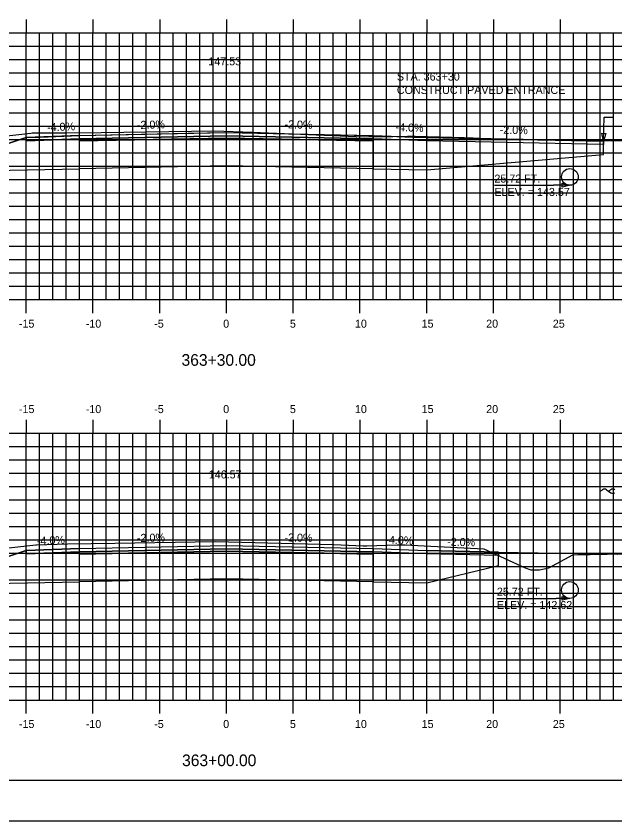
# Model space of a CAD drawing. Extents: x 1146968 to 1147138, y 608981 to 609091.
# Drawn here: x 1147035.4 to 1147080.3, y 608981.3 to 609041.6 of the extents above; entities that cross this region are included whole.
import ezdxf

# ---------------------------------------------------------------- set-up
doc = ezdxf.new("R2010")
doc.units = 0
for name, color, linetype in [('ANNOTATION', 7, 'Continuous'), ('BORDER', 7, 'Continuous'), ('D_Drainage_Culvert', 7, 'Continuous'), ('D_Roadway_Centerline', 7, 'Continuous'), ('D_Roadway_Centerline_Text', 7, 'Continuous'), ('D_Roadway_Edge_Shoulder', 7, 'Continuous'), ('D_Roadway_Edge_TW', 7, 'Continuous'), ('D_Roadway_Pavement', 7, 'Continuous'), ('D_Roadway_SubGrade', 7, 'Continuous'), ('D_Text_Standard', 7, 'Continuous'), ('D_Utilities_Pole_Joint_Rt', 7, 'Continuous'), ('H_V ANNOTATION', 7, 'Continuous'), ('MAJOR', 7, 'Continuous'), ('MINOR', 7, 'Continuous'), ('PLOT BOUNDARY', 7, 'Continuous'), ('S_Roadway_Centerline', 7, 'Continuous')]:
    doc.layers.add(name, color=color, linetype=linetype)

msp = doc.modelspace()

# ---------------------------------------------------------------- linework, layer by layer
for points in [[(1147030.469, 609030.576), (1147036.183, 609032.48), (1147036.184, 609032.48), (1147036.184, 609032.48), (1147037.225, 609032.522), (1147040.184, 609032.64), (1147048.322, 609032.803), (1147051.184, 609032.86), (1147059.322, 609032.697), (1147062.184, 609032.64), (1147065.144, 609032.522), (1147066.184, 609032.48), (1147075.982, 609032.284), (1147079.429, 609032.215)], [(1147013.409, 609002.682), (1147014.659, 609002.625), (1147015.909, 609002.405), (1147017.159, 609002.023), (1147018.409, 609001.479), (1147025.46, 608997.953), (1147028.46, 608998.953), (1147036.183, 609001.528), (1147036.184, 609001.528), (1147040.184, 609001.688), (1147051.184, 609001.908), (1147062.184, 609001.688), (1147066.184, 609001.528), (1147071.549, 609001.42)]]:
    msp.add_lwpolyline(points)
at = {"layer": 'BORDER'}
msp.add_lwpolyline([(1146976.185, 608984.335), (1147136.185, 608984.335), (1147136.185, 609089.335), (1146976.185, 609089.335)], close=True, dxfattribs=at)
at = {"layer": 'D_Drainage_Culvert'}
for centre in [(1147076.908, 609029.531), (1147076.908, 608998.578)]:
    msp.add_circle(centre, 0.625, dxfattribs=at)
at = {"layer": 'D_Roadway_Edge_Shoulder'}
for points in [[(1147040.184, 609032.64), (1147036.184, 609032.48), (1147036.184, 609032.23), (1147040.184, 609032.39)], [(1147062.184, 609032.64), (1147066.184, 609032.48), (1147066.184, 609032.23), (1147062.184, 609032.39)], [(1147066.184, 609032.48), (1147079.429, 609032.215), (1147079.429, 609031.965), (1147066.184, 609032.23)], [(1147040.184, 609001.688), (1147036.184, 609001.528), (1147036.184, 609001.278), (1147040.184, 609001.438)], [(1147062.184, 609001.688), (1147066.184, 609001.528), (1147066.184, 609001.278), (1147062.184, 609001.438)], [(1147066.184, 609001.528), (1147071.549, 609001.42), (1147071.549, 609001.17), (1147066.184, 609001.278)]]:
    msp.add_lwpolyline(points, close=True, dxfattribs=at)
at = {"layer": 'D_Roadway_Edge_TW'}
for points in [[(1147040.184, 609032.39), (1147040.184, 609032.64), (1147051.184, 609032.86), (1147062.184, 609032.64), (1147062.184, 609032.39), (1147051.184, 609032.61)], [(1147040.184, 609001.438), (1147040.184, 609001.688), (1147051.184, 609001.908), (1147062.184, 609001.688), (1147062.184, 609001.438), (1147051.184, 609001.658)]]:
    msp.add_lwpolyline(points, close=True, dxfattribs=at)
at = {"layer": 'D_Roadway_Pavement'}
for points in [[(1147040.184, 609032.223), (1147040.184, 609032.39), (1147051.184, 609032.61), (1147062.184, 609032.39), (1147062.184, 609032.223), (1147051.184, 609032.443)], [(1147040.184, 609001.271), (1147040.184, 609001.438), (1147051.184, 609001.658), (1147062.184, 609001.438), (1147062.184, 609001.271), (1147051.184, 609001.491)]]:
    msp.add_lwpolyline(points, close=True, dxfattribs=at)
at = {"layer": 'D_Roadway_SubGrade'}
msp.add_line((1147071.549, 609001.42), (1147080.474, 609001.271), dxfattribs=at)
for points in [[(1147040.184, 609032.223), (1147040.184, 609032.39), (1147036.184, 609032.23), (1147036.184, 609032.48), (1147036.183, 609032.48), (1147028.46, 609029.906), (1147040.184, 609030.14)], [(1147040.184, 609030.14), (1147040.184, 609032.223), (1147051.184, 609032.443), (1147062.184, 609032.223), (1147062.184, 609030.14), (1147051.184, 609030.36)], [(1147079.429, 609031.215), (1147079.429, 609032.215), (1147066.184, 609032.48), (1147066.184, 609032.23), (1147062.184, 609032.39), (1147062.184, 609032.223), (1147062.184, 609030.14), (1147066.184, 609030.06)], [(1147040.184, 609001.271), (1147040.184, 609001.438), (1147036.184, 609001.278), (1147036.184, 609001.528), (1147036.183, 609001.528), (1147028.46, 608998.953), (1147040.184, 608999.188)], [(1147040.184, 608999.188), (1147040.184, 609001.271), (1147051.184, 609001.491), (1147062.184, 609001.271), (1147062.184, 608999.188), (1147051.184, 608999.408)], [(1147071.549, 609000.42), (1147071.549, 609001.42), (1147066.184, 609001.528), (1147066.184, 609001.278), (1147062.184, 609001.438), (1147062.184, 609001.271), (1147062.184, 608999.188), (1147066.184, 608999.108)]]:
    msp.add_lwpolyline(points, close=True, dxfattribs=at)
at = {"layer": 'D_Text_Standard'}
for p, q in [((1147071.256, 609028.906), (1147075.692, 609028.906)), ((1147071.439, 608997.953), (1147075.875, 608997.953))]:
    msp.add_line(p, q, dxfattribs=at)
for points in [[(1147079.429, 609032.215), (1147079.466, 609033.997), (1147080.146, 609033.997)], [(1147076.908, 609028.906), (1147076.372, 609028.906), (1147075.692, 609028.906)], [(1147076.908, 608997.953), (1147076.555, 608997.953), (1147075.875, 608997.953)]]:
    msp.add_lwpolyline(points, dxfattribs=at)
for points in [[(1147079.429, 609032.215), (1147079.296, 609032.8), (1147079.587, 609032.794)], [(1147076.908, 609028.906), (1147076.326, 609028.76), (1147076.326, 609029.051)], [(1147076.908, 608997.953), (1147076.326, 608997.808), (1147076.326, 608998.099)]]:
    msp.add_lwpolyline(points, close=True, dxfattribs=at)
at = {"layer": 'D_Utilities_Pole_Joint_Rt'}
for p, q in [((1147079.184, 609005.978), (1147079.34, 609006.088)), ((1147079.184, 609001.22), (1147079.184, 609005.978)), ((1147079.653, 609006.088), (1147079.809, 609005.978)), ((1147079.965, 609006.088), (1147079.809, 609005.978)), ((1147079.809, 609005.978), (1147079.965, 609005.867))]:
    msp.add_line(p, q, dxfattribs=at)
for centre, start, end in [((1147079.497, 609005.867), 90, 125.26439), ((1147079.497, 609005.867), 54.73561, 90), ((1147080.122, 609005.867), 90, 125.26439), ((1147080.122, 609006.088), 234.73561, 270), ((1147080.122, 609005.867), 54.73561, 90), ((1147080.122, 609006.088), 270, 305.26439)]:
    msp.add_arc(centre, 0.271, start, end, dxfattribs=at)
at = {"layer": 'MAJOR'}
for p, q in [((1147036.184, 609041.337), (1147036.184, 609040.335)), ((1147041.184, 609041.337), (1147041.184, 609040.335)), ((1147046.184, 609041.337), (1147046.184, 609040.335)), ((1147051.184, 609041.337), (1147051.184, 609040.335)), ((1147056.184, 609041.337), (1147056.184, 609040.335)), ((1147061.184, 609041.337), (1147061.184, 609040.335)), ((1147066.184, 609041.337), (1147066.184, 609040.335)), ((1147071.184, 609041.337), (1147071.184, 609040.335)), ((1147076.184, 609041.337), (1147076.184, 609040.335)), ((1146981.184, 609040.335), (1147121.184, 609040.335)), ((1146981.184, 609040.335), (1147121.184, 609040.335)), ((1147036.184, 609020.335), (1147036.184, 609040.335)), ((1147041.184, 609020.335), (1147041.184, 609040.335)), ((1147046.184, 609020.335), (1147046.184, 609040.335)), ((1147051.184, 609020.335), (1147051.184, 609040.335)), ((1147056.184, 609020.335), (1147056.184, 609040.335)), ((1147061.184, 609020.335), (1147061.184, 609040.335)), ((1147066.184, 609020.335), (1147066.184, 609040.335)), ((1147071.184, 609020.335), (1147071.184, 609040.335)), ((1147076.184, 609020.335), (1147076.184, 609040.335)), ((1146981.184, 609035.335), (1147121.184, 609035.335)), ((1146981.184, 609030.335), (1147121.184, 609030.335)), ((1146981.184, 609025.335), (1147121.184, 609025.335)), ((1146981.184, 609020.335), (1147121.184, 609020.335)), ((1146981.184, 609020.335), (1147121.184, 609020.335)), ((1147036.184, 609019.333), (1147036.184, 609020.335)), ((1147041.184, 609019.333), (1147041.184, 609020.335)), ((1147046.184, 609019.333), (1147046.184, 609020.335)), ((1147051.184, 609019.333), (1147051.184, 609020.335)), ((1147056.184, 609019.333), (1147056.184, 609020.335)), ((1147061.184, 609019.333), (1147061.184, 609020.335)), ((1147066.184, 609019.333), (1147066.184, 609020.335)), ((1147071.184, 609019.333), (1147071.184, 609020.335)), ((1147076.184, 609019.333), (1147076.184, 609020.335)), ((1147036.184, 609011.337), (1147036.184, 609010.335)), ((1147041.184, 609011.337), (1147041.184, 609010.335)), ((1147046.184, 609011.337), (1147046.184, 609010.335)), ((1147051.184, 609011.337), (1147051.184, 609010.335)), ((1147056.184, 609011.337), (1147056.184, 609010.335)), ((1147061.184, 609011.337), (1147061.184, 609010.335)), ((1147066.184, 609011.337), (1147066.184, 609010.335)), ((1147071.184, 609011.337), (1147071.184, 609010.335)), ((1147076.184, 609011.337), (1147076.184, 609010.335)), ((1146981.184, 609010.335), (1147121.184, 609010.335)), ((1146981.184, 609010.335), (1147121.184, 609010.335)), ((1147036.184, 608990.335), (1147036.184, 609010.335)), ((1147041.184, 608990.335), (1147041.184, 609010.335)), ((1147046.184, 608990.335), (1147046.184, 609010.335)), ((1147051.184, 608990.335), (1147051.184, 609010.335)), ((1147056.184, 608990.335), (1147056.184, 609010.335)), ((1147061.184, 608990.335), (1147061.184, 609010.335)), ((1147066.184, 608990.335), (1147066.184, 609010.335)), ((1147071.184, 608990.335), (1147071.184, 609010.335)), ((1147076.184, 608990.335), (1147076.184, 609010.335)), ((1146981.184, 609005.335), (1147121.184, 609005.335)), ((1146981.184, 609000.335), (1147121.184, 609000.335)), ((1146981.184, 608995.335), (1147121.184, 608995.335)), ((1146981.184, 608990.335), (1147121.184, 608990.335)), ((1146981.184, 608990.335), (1147121.184, 608990.335)), ((1147036.184, 608989.333), (1147036.184, 608990.335)), ((1147041.184, 608989.333), (1147041.184, 608990.335)), ((1147046.184, 608989.333), (1147046.184, 608990.335)), ((1147051.184, 608989.333), (1147051.184, 608990.335)), ((1147056.184, 608989.333), (1147056.184, 608990.335)), ((1147061.184, 608989.333), (1147061.184, 608990.335)), ((1147066.184, 608989.333), (1147066.184, 608990.335)), ((1147071.184, 608989.333), (1147071.184, 608990.335)), ((1147076.184, 608989.333), (1147076.184, 608990.335))]:
    msp.add_line(p, q, dxfattribs=at)
at = {"layer": 'MINOR'}
for p, q in [((1147037.184, 609020.335), (1147037.184, 609040.335)), ((1147038.184, 609020.335), (1147038.184, 609040.335)), ((1147039.184, 609020.335), (1147039.184, 609040.335)), ((1147040.184, 609020.335), (1147040.184, 609040.335)), ((1147042.184, 609020.335), (1147042.184, 609040.335)), ((1147043.184, 609020.335), (1147043.184, 609040.335)), ((1147044.184, 609020.335), (1147044.184, 609040.335)), ((1147045.184, 609020.335), (1147045.184, 609040.335)), ((1147047.184, 609020.335), (1147047.184, 609040.335)), ((1147048.184, 609020.335), (1147048.184, 609040.335)), ((1147049.184, 609020.335), (1147049.184, 609040.335)), ((1147050.184, 609020.335), (1147050.184, 609040.335)), ((1147052.184, 609020.335), (1147052.184, 609040.335)), ((1147053.184, 609020.335), (1147053.184, 609040.335)), ((1147054.184, 609020.335), (1147054.184, 609040.335)), ((1147055.184, 609020.335), (1147055.184, 609040.335)), ((1147057.184, 609020.335), (1147057.184, 609040.335)), ((1147058.184, 609020.335), (1147058.184, 609040.335)), ((1147059.184, 609020.335), (1147059.184, 609040.335)), ((1147060.184, 609020.335), (1147060.184, 609040.335)), ((1147062.184, 609020.335), (1147062.184, 609040.335)), ((1147063.184, 609020.335), (1147063.184, 609040.335)), ((1147064.184, 609020.335), (1147064.184, 609040.335)), ((1147065.184, 609020.335), (1147065.184, 609040.335)), ((1147067.184, 609020.335), (1147067.184, 609040.335)), ((1147068.184, 609020.335), (1147068.184, 609040.335)), ((1147069.184, 609020.335), (1147069.184, 609040.335)), ((1147070.184, 609020.335), (1147070.184, 609040.335)), ((1147072.184, 609020.335), (1147072.184, 609040.335)), ((1147073.184, 609020.335), (1147073.184, 609040.335)), ((1147074.184, 609020.335), (1147074.184, 609040.335)), ((1147075.184, 609020.335), (1147075.184, 609040.335)), ((1147077.184, 609020.335), (1147077.184, 609040.335)), ((1147078.184, 609020.335), (1147078.184, 609040.335)), ((1147079.184, 609020.335), (1147079.184, 609040.335)), ((1147080.184, 609020.335), (1147080.184, 609040.335)), ((1146981.184, 609039.335), (1147121.184, 609039.335)), ((1146981.184, 609038.335), (1147121.184, 609038.335)), ((1146981.184, 609037.335), (1147121.184, 609037.335)), ((1146981.184, 609036.335), (1147121.184, 609036.335)), ((1146981.184, 609034.335), (1147121.184, 609034.335)), ((1146981.184, 609033.335), (1147121.184, 609033.335)), ((1146981.184, 609032.335), (1147121.184, 609032.335)), ((1146981.184, 609031.335), (1147121.184, 609031.335)), ((1146981.184, 609029.335), (1147121.184, 609029.335)), ((1146981.184, 609028.335), (1147121.184, 609028.335)), ((1146981.184, 609027.335), (1147121.184, 609027.335)), ((1146981.184, 609026.335), (1147121.184, 609026.335)), ((1146981.184, 609024.335), (1147121.184, 609024.335)), ((1146981.184, 609023.335), (1147121.184, 609023.335)), ((1146981.184, 609022.335), (1147121.184, 609022.335)), ((1146981.184, 609021.335), (1147121.184, 609021.335)), ((1147037.184, 608990.335), (1147037.184, 609010.335)), ((1147038.184, 608990.335), (1147038.184, 609010.335)), ((1147039.184, 608990.335), (1147039.184, 609010.335)), ((1147040.184, 608990.335), (1147040.184, 609010.335)), ((1147042.184, 608990.335), (1147042.184, 609010.335)), ((1147043.184, 608990.335), (1147043.184, 609010.335)), ((1147044.184, 608990.335), (1147044.184, 609010.335)), ((1147045.184, 608990.335), (1147045.184, 609010.335)), ((1147047.184, 608990.335), (1147047.184, 609010.335)), ((1147048.184, 608990.335), (1147048.184, 609010.335)), ((1147049.184, 608990.335), (1147049.184, 609010.335)), ((1147050.184, 608990.335), (1147050.184, 609010.335)), ((1147052.184, 608990.335), (1147052.184, 609010.335)), ((1147053.184, 608990.335), (1147053.184, 609010.335)), ((1147054.184, 608990.335), (1147054.184, 609010.335)), ((1147055.184, 608990.335), (1147055.184, 609010.335)), ((1147057.184, 608990.335), (1147057.184, 609010.335)), ((1147058.184, 608990.335), (1147058.184, 609010.335)), ((1147059.184, 608990.335), (1147059.184, 609010.335)), ((1147060.184, 608990.335), (1147060.184, 609010.335)), ((1147062.184, 608990.335), (1147062.184, 609010.335)), ((1147063.184, 608990.335), (1147063.184, 609010.335)), ((1147064.184, 608990.335), (1147064.184, 609010.335)), ((1147065.184, 608990.335), (1147065.184, 609010.335)), ((1147067.184, 608990.335), (1147067.184, 609010.335)), ((1147068.184, 608990.335), (1147068.184, 609010.335)), ((1147069.184, 608990.335), (1147069.184, 609010.335)), ((1147070.184, 608990.335), (1147070.184, 609010.335)), ((1147072.184, 608990.335), (1147072.184, 609010.335)), ((1147073.184, 608990.335), (1147073.184, 609010.335)), ((1147074.184, 608990.335), (1147074.184, 609010.335)), ((1147075.184, 608990.335), (1147075.184, 609010.335)), ((1147077.184, 608990.335), (1147077.184, 609010.335)), ((1147078.184, 608990.335), (1147078.184, 609010.335)), ((1147079.184, 608990.335), (1147079.184, 609010.335)), ((1147080.184, 608990.335), (1147080.184, 609010.335)), ((1146981.184, 609009.335), (1147121.184, 609009.335)), ((1146981.184, 609008.335), (1147121.184, 609008.335)), ((1146981.184, 609007.335), (1147121.184, 609007.335)), ((1146981.184, 609006.335), (1147121.184, 609006.335)), ((1146981.184, 609004.335), (1147121.184, 609004.335)), ((1146981.184, 609003.335), (1147121.184, 609003.335)), ((1146981.184, 609002.335), (1147121.184, 609002.335)), ((1146981.184, 609001.335), (1147121.184, 609001.335)), ((1146981.184, 608999.335), (1147121.184, 608999.335)), ((1146981.184, 608998.335), (1147121.184, 608998.335)), ((1146981.184, 608997.335), (1147121.184, 608997.335)), ((1146981.184, 608996.335), (1147121.184, 608996.335)), ((1146981.184, 608994.335), (1147121.184, 608994.335)), ((1146981.184, 608993.335), (1147121.184, 608993.335)), ((1146981.184, 608992.335), (1147121.184, 608992.335)), ((1146981.184, 608991.335), (1147121.184, 608991.335))]:
    msp.add_line(p, q, dxfattribs=at)
at = {"layer": 'PLOT BOUNDARY'}
msp.add_lwpolyline([(1146968.091, 608981.276), (1147138.091, 608981.276), (1147138.091, 609091.276), (1146968.091, 609091.276)], close=True, dxfattribs=at)
at = {"layer": 'S_Roadway_Centerline'}
for points in [[(1147032.902, 609032.414), (1147036.544, 609032.814), (1147036.638, 609032.827), (1147036.717, 609032.828), (1147039.178, 609032.83), (1147041.813, 609032.859), (1147050.267, 609032.976), (1147053.128, 609032.886), (1147061.491, 609032.54), (1147061.851, 609032.551), (1147063.335, 609032.563), (1147063.654, 609032.562), (1147064.737, 609032.597), (1147065.095, 609032.59), (1147065.314, 609032.584), (1147068.986, 609032.481), (1147069.403, 609032.467), (1147069.668, 609032.456), (1147071.555, 609032.368), (1147074.477, 609032.306), (1147081.694, 609032.225)], [(1147032.634, 609001.482), (1147036.91, 609001.96), (1147036.935, 609001.963), (1147036.96, 609001.964), (1147039.276, 609002.034), (1147042.815, 609002.088), (1147050.33, 609002.201), (1147059.222, 609001.979), (1147061.413, 609001.889), (1147061.458, 609001.89), (1147061.646, 609001.892), (1147061.687, 609001.891), (1147063.974, 609001.967), (1147063.981, 609001.967), (1147063.986, 609001.967), (1147064.574, 609001.95), (1147065.987, 609001.886), (1147070.463, 609001.666), (1147073.56, 609000.239), (1147073.991, 609000.098), (1147074.629, 609000.08), (1147075.325, 609000.242), (1147077.117, 609001.224), (1147081.001, 609001.278)]]:
    msp.add_lwpolyline(points, dxfattribs=at)

# ---------------------------------------------------------------- texts
at = {"layer": 'ANNOTATION'}
for s, p in [('STA. 363+30', (1147063.95, 609036.749)), ('CONSTRUCT PAVED ENTRANCE', (1147063.95, 609035.747))]:
    msp.add_text(s, height=0.6, dxfattribs=at).set_placement(p)
for s, rotation, p in [('-4.0%', 2.29061, (1147037.76, 609032.944)), ('-2.0%', 1.14576, (1147044.487, 609033.126)), ('-2.0%', 358.85424, (1147055.527, 609033.174)), ('-4.0%', 357.70939, (1147063.84, 609032.975)), ('-2.0%', 358.85424, (1147071.65, 609032.771)), ('-4.0%', 2.29061, (1147037, 609001.961)), ('-2.0%', 1.14576, (1147044.487, 609002.174)), ('-2.0%', 358.85424, (1147055.527, 609002.221)), ('-4.0%', 357.70939, (1147063.08, 609002.053)), ('-2.0%', 358.85424, (1147067.71, 609001.897))]:
    msp.add_text(s, height=0.6, rotation=rotation, dxfattribs=at).set_placement(p)
at = {"layer": 'D_Roadway_Centerline'}
for s, p in [('C', (1147051.179, 609032.86)), ('L', (1147051.184, 609032.853)), ('C', (1147051.179, 609001.908)), ('L', (1147051.184, 609001.9))]:
    msp.add_text(s, height=0.0146, dxfattribs=at).set_placement(p)
at = {"layer": 'D_Roadway_Centerline_Text'}
for s, p in [('147.53', (1147049.828, 609037.892)), ('146.57', (1147049.863, 609006.94))]:
    msp.add_text(s, height=0.6, dxfattribs=at).set_placement(p)
at = {"layer": 'D_Text_Standard'}
for s, p in [('25.72 FT.', (1147071.256, 609029.106)), ('ELEV. = 143.57', (1147071.256, 609028.106)), ('25.72 FT.', (1147071.439, 608998.153)), ('ELEV. = 142.62', (1147071.439, 608997.153))]:
    msp.add_text(s, height=0.6, dxfattribs=at).set_placement(p)
at = {"layer": 'H_V ANNOTATION'}
for s, height, p in [('-15', 0.6, (1147035.641, 609018.235)), ('-10', 0.6, (1147040.649, 609018.235)), ('-5', 0.6, (1147045.775, 609018.235)), ('0', 0.6, (1147050.943, 609018.235)), ('5', 0.6, (1147055.935, 609018.235)), ('10', 0.6, (1147060.81, 609018.235)), ('15', 0.6, (1147065.802, 609018.235)), ('20', 0.6, (1147070.638, 609018.235)), ('25', 0.6, (1147075.63, 609018.235)), ('363+30.00', 0.875, (1147047.821, 609015.378)), ('-15', 0.6, (1147035.641, 609011.835)), ('-10', 0.6, (1147040.649, 609011.835)), ('-5', 0.6, (1147045.775, 609011.835)), ('0', 0.6, (1147050.943, 609011.835)), ('5', 0.6, (1147055.935, 609011.835)), ('10', 0.6, (1147060.81, 609011.835)), ('15', 0.6, (1147065.802, 609011.835)), ('20', 0.6, (1147070.638, 609011.835)), ('25', 0.6, (1147075.63, 609011.835)), ('-15', 0.6, (1147035.641, 608988.235)), ('-10', 0.6, (1147040.649, 608988.235)), ('-5', 0.6, (1147045.775, 608988.235)), ('0', 0.6, (1147050.943, 608988.235)), ('5', 0.6, (1147055.935, 608988.235)), ('10', 0.6, (1147060.81, 608988.235)), ('15', 0.6, (1147065.802, 608988.235)), ('20', 0.6, (1147070.638, 608988.235)), ('25', 0.6, (1147075.63, 608988.235)), ('363+00.00', 0.875, (1147047.86, 608985.378))]:
    msp.add_text(s, height=height, dxfattribs=at).set_placement(p)
at = {"layer": 'S_Roadway_Centerline'}
for s, p in [('L', (1147050.259, 609032.969)), ('C', (1147050.262, 609032.976)), ('L', (1147050.322, 609002.194)), ('C', (1147050.325, 609002.201))]:
    msp.add_text(s, height=0.0146, dxfattribs=at).set_placement(p)

doc.saveas('drawing.dxf')
